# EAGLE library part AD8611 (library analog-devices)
Ultrafast 4 ns Single Supply Comparators Source: http://www.analog.com/UploadedFiles/Data_Sheets/703465986AD8611_2_0.pdf Upgrade for LT1394 and LT1016 Designs
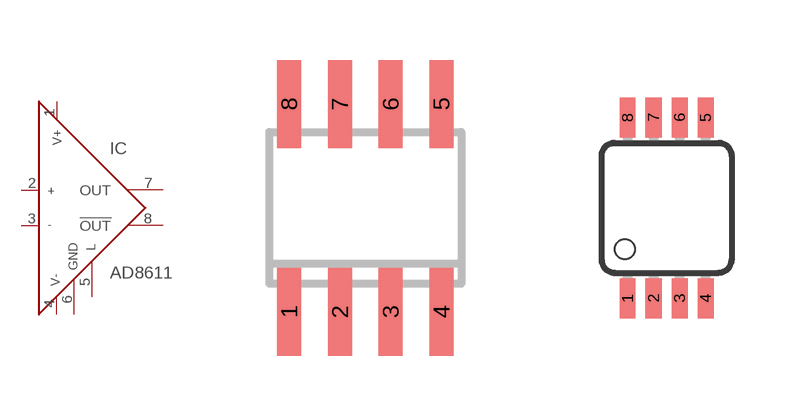
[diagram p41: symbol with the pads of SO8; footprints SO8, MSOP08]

Designator prefix IC

## AD8611R (MPN: AD8611ARMZ-R2; OC_FARNELL: 1319472; OC_NEWARK: 19M8930)  [SO8]
1  V+  pwr
2  IN+  in
3  IN-  in
4  V-  pwr
5  L  in
6  GND  pwr
7  OUT  out
8  !OUT  out

## AD8611RM (MPN: AD8611ARMZ-R2; OC_FARNELL: 1464995; OC_NEWARK: 19M8930)  [MSOP08]
Pads as for SO8

## Footprint SO8 (pad centres in mm)
8-Lead Small Outline IC (SO-8) Source: http://www.analog.com/UploadedFiles/Data_Sheets/703465986AD8611_2_0.pdf
smd 0.6 x 2.2: 1 -1.905,-2.6; 2 -0.635,-2.6; 3 0.635,-2.6; 4 1.905,-2.6; 5 1.905,2.6; 6 0.635,2.6; 7 -0.635,2.6; 8 -1.905,2.6

## Footprint MSOP08 (pad centres in mm)
8-Lead micro SO (RM-8) Source: http://www.analog.com/UploadedFiles/Data_Sheets/703465986AD8611_2_0.pdf
smd 0.4 x 1: 1 -0.976,-2.263; 2 -0.326,-2.263; 3 0.324,-2.263; 4 0.974,-2.263; 5 0.974,2.262; 6 0.324,2.262; 7 -0.326,2.262; 8 -0.976,2.262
